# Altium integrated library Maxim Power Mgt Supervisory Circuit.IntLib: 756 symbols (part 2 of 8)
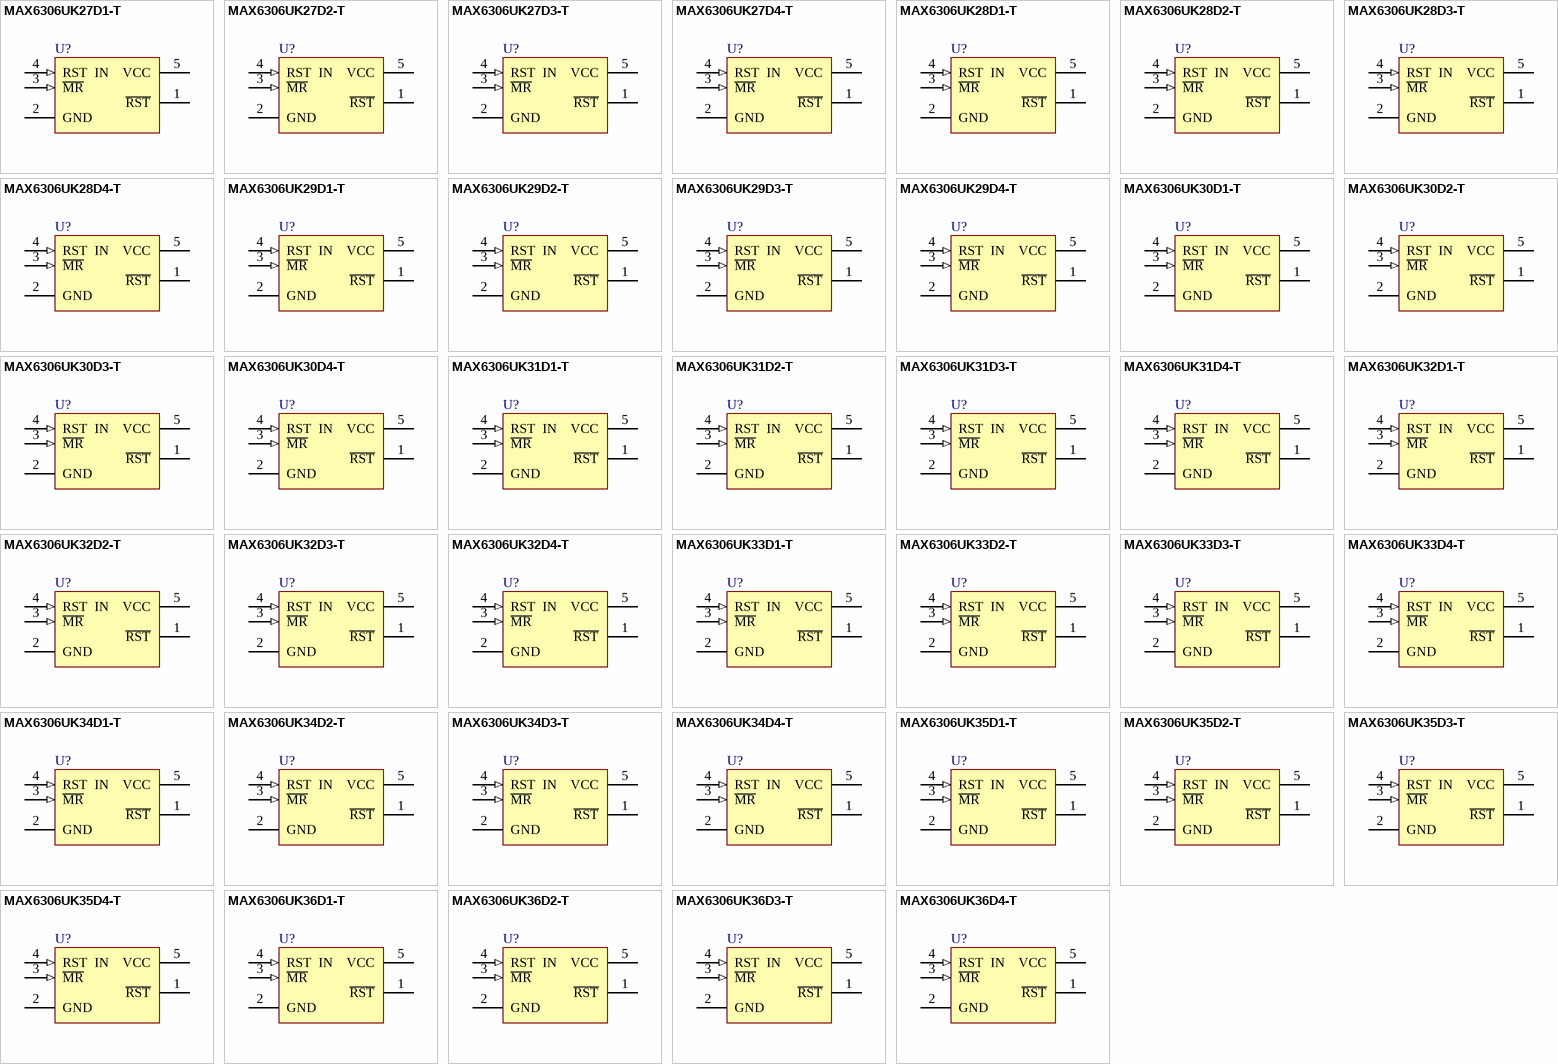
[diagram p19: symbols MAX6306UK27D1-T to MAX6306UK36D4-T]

## MAX6306UK34D4-T
designator U?
5-Pin, Multiple-Input, Programmable Reset IC
footprint SOT23-5_N (SOT23, 5-Leads, Body 2.9x1.6mm, Pitch 0.95mm, Lead Span 2.8mm, IPC Medium Density)
footprint SOT23-5_L (SOT23, 5-Leads, Body 2.9x1.6mm, Pitch 0.95mm, Lead Span 2.8mm, IPC High Density)
footprint SOT23-5_M (SOT23, 5-Leads, Body 2.9x1.6mm, Pitch 0.95mm, Lead Span 2.8mm, IPC Low Density)
pins: 1 ~{RST} (oc), 2 GND (power), 3 ~{MR} (in), 4 RST  IN (in), 5 VCC (power)

## MAX6306UK35D1-T
designator U?
5-Pin, Multiple-Input, Programmable Reset IC
footprint SOT23-5_N (SOT23, 5-Leads, Body 2.9x1.6mm, Pitch 0.95mm, Lead Span 2.8mm, IPC Medium Density)
footprint SOT23-5_L (SOT23, 5-Leads, Body 2.9x1.6mm, Pitch 0.95mm, Lead Span 2.8mm, IPC High Density)
footprint SOT23-5_M (SOT23, 5-Leads, Body 2.9x1.6mm, Pitch 0.95mm, Lead Span 2.8mm, IPC Low Density)
pins: 1 ~{RST} (oc), 2 GND (power), 3 ~{MR} (in), 4 RST  IN (in), 5 VCC (power)

## MAX6306UK35D2-T
designator U?
5-Pin, Multiple-Input, Programmable Reset IC
footprint SOT23-5_N (SOT23, 5-Leads, Body 2.9x1.6mm, Pitch 0.95mm, Lead Span 2.8mm, IPC Medium Density)
footprint SOT23-5_L (SOT23, 5-Leads, Body 2.9x1.6mm, Pitch 0.95mm, Lead Span 2.8mm, IPC High Density)
footprint SOT23-5_M (SOT23, 5-Leads, Body 2.9x1.6mm, Pitch 0.95mm, Lead Span 2.8mm, IPC Low Density)
pins: 1 ~{RST} (oc), 2 GND (power), 3 ~{MR} (in), 4 RST  IN (in), 5 VCC (power)

## MAX6306UK35D3-T
designator U?
5-Pin, Multiple-Input, Programmable Reset IC
footprint SOT23-5_N (SOT23, 5-Leads, Body 2.9x1.6mm, Pitch 0.95mm, Lead Span 2.8mm, IPC Medium Density)
footprint SOT23-5_L (SOT23, 5-Leads, Body 2.9x1.6mm, Pitch 0.95mm, Lead Span 2.8mm, IPC High Density)
footprint SOT23-5_M (SOT23, 5-Leads, Body 2.9x1.6mm, Pitch 0.95mm, Lead Span 2.8mm, IPC Low Density)
pins: 1 ~{RST} (oc), 2 GND (power), 3 ~{MR} (in), 4 RST  IN (in), 5 VCC (power)

## MAX6306UK35D4-T
designator U?
5-Pin, Multiple-Input, Programmable Reset IC
footprint SOT23-5_N (SOT23, 5-Leads, Body 2.9x1.6mm, Pitch 0.95mm, Lead Span 2.8mm, IPC Medium Density)
footprint SOT23-5_L (SOT23, 5-Leads, Body 2.9x1.6mm, Pitch 0.95mm, Lead Span 2.8mm, IPC High Density)
footprint SOT23-5_M (SOT23, 5-Leads, Body 2.9x1.6mm, Pitch 0.95mm, Lead Span 2.8mm, IPC Low Density)
pins: 1 ~{RST} (oc), 2 GND (power), 3 ~{MR} (in), 4 RST  IN (in), 5 VCC (power)

## MAX6306UK36D1-T
designator U?
5-Pin, Multiple-Input, Programmable Reset IC
footprint SOT23-5_N (SOT23, 5-Leads, Body 2.9x1.6mm, Pitch 0.95mm, Lead Span 2.8mm, IPC Medium Density)
footprint SOT23-5_L (SOT23, 5-Leads, Body 2.9x1.6mm, Pitch 0.95mm, Lead Span 2.8mm, IPC High Density)
footprint SOT23-5_M (SOT23, 5-Leads, Body 2.9x1.6mm, Pitch 0.95mm, Lead Span 2.8mm, IPC Low Density)
pins: 1 ~{RST} (oc), 2 GND (power), 3 ~{MR} (in), 4 RST  IN (in), 5 VCC (power)

## MAX6306UK36D2-T
designator U?
5-Pin, Multiple-Input, Programmable Reset IC
footprint SOT23-5_N (SOT23, 5-Leads, Body 2.9x1.6mm, Pitch 0.95mm, Lead Span 2.8mm, IPC Medium Density)
footprint SOT23-5_L (SOT23, 5-Leads, Body 2.9x1.6mm, Pitch 0.95mm, Lead Span 2.8mm, IPC High Density)
footprint SOT23-5_M (SOT23, 5-Leads, Body 2.9x1.6mm, Pitch 0.95mm, Lead Span 2.8mm, IPC Low Density)
pins: 1 ~{RST} (oc), 2 GND (power), 3 ~{MR} (in), 4 RST  IN (in), 5 VCC (power)

## MAX6306UK36D3-T
designator U?
5-Pin, Multiple-Input, Programmable Reset IC
footprint SOT23-5_N (SOT23, 5-Leads, Body 2.9x1.6mm, Pitch 0.95mm, Lead Span 2.8mm, IPC Medium Density)
footprint SOT23-5_L (SOT23, 5-Leads, Body 2.9x1.6mm, Pitch 0.95mm, Lead Span 2.8mm, IPC High Density)
footprint SOT23-5_M (SOT23, 5-Leads, Body 2.9x1.6mm, Pitch 0.95mm, Lead Span 2.8mm, IPC Low Density)
pins: 1 ~{RST} (oc), 2 GND (power), 3 ~{MR} (in), 4 RST  IN (in), 5 VCC (power)

## MAX6306UK36D4-T
designator U?
5-Pin, Multiple-Input, Programmable Reset IC
footprint SOT23-5_N (SOT23, 5-Leads, Body 2.9x1.6mm, Pitch 0.95mm, Lead Span 2.8mm, IPC Medium Density)
footprint SOT23-5_L (SOT23, 5-Leads, Body 2.9x1.6mm, Pitch 0.95mm, Lead Span 2.8mm, IPC High Density)
footprint SOT23-5_M (SOT23, 5-Leads, Body 2.9x1.6mm, Pitch 0.95mm, Lead Span 2.8mm, IPC Low Density)
pins: 1 ~{RST} (oc), 2 GND (power), 3 ~{MR} (in), 4 RST  IN (in), 5 VCC (power)

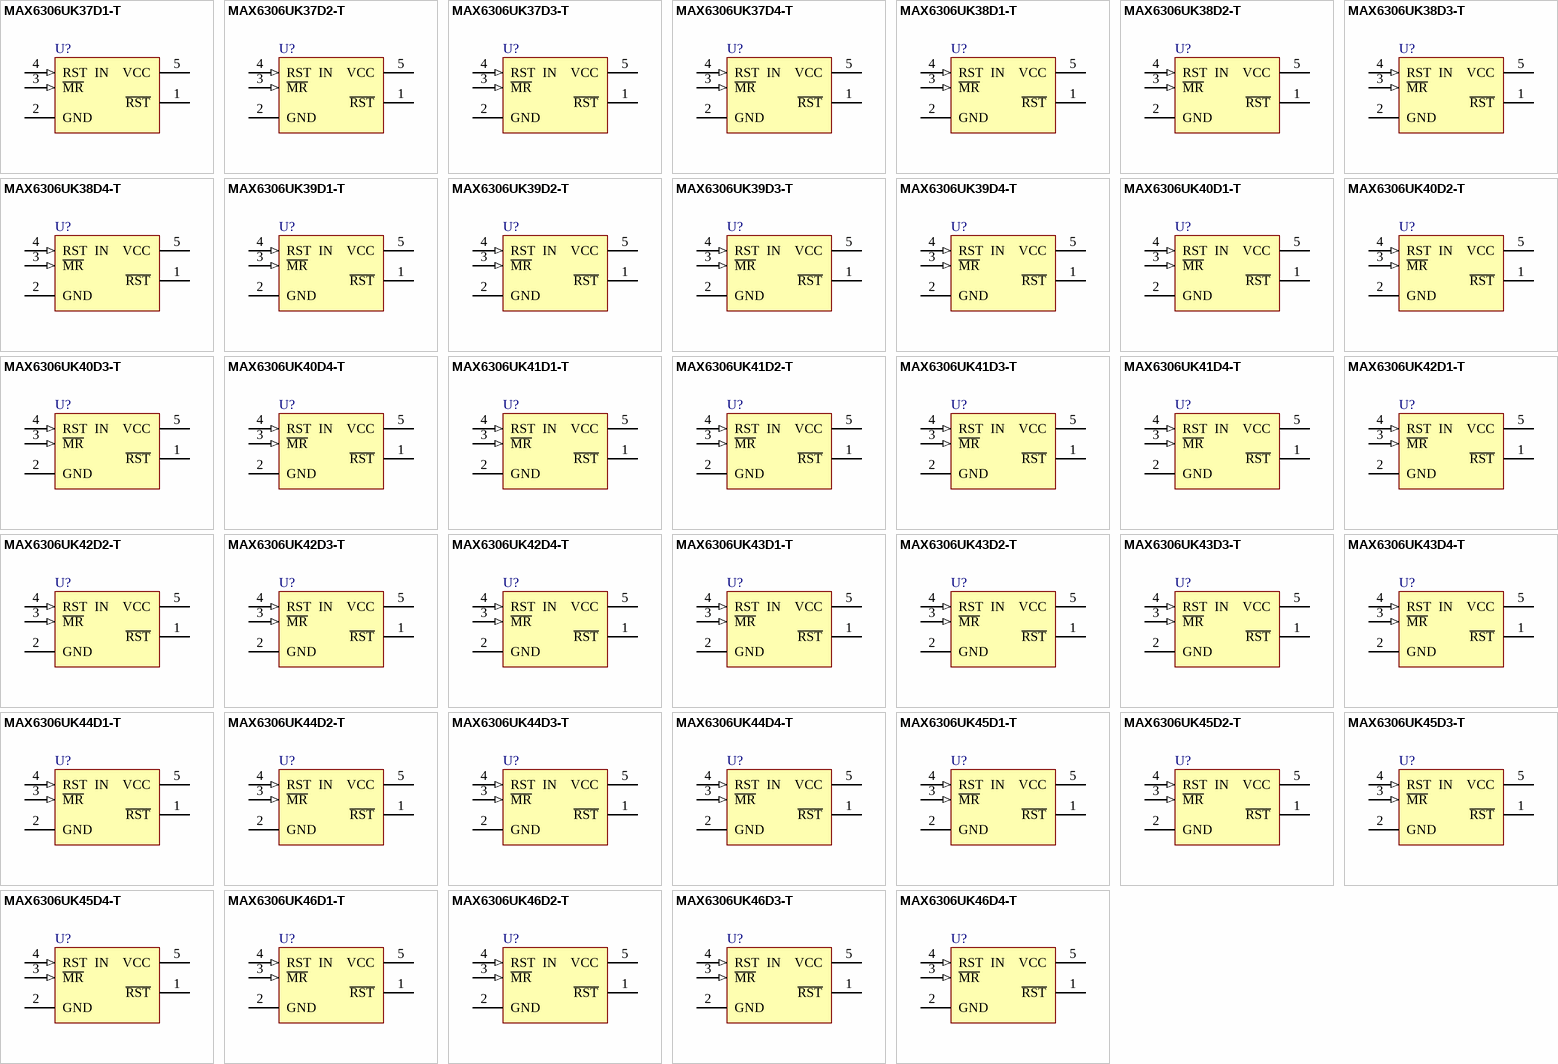
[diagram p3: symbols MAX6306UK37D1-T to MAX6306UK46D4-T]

## MAX6306UK37D1-T
designator U?
5-Pin, Multiple-Input, Programmable Reset IC
footprint SOT23-5_N (SOT23, 5-Leads, Body 2.9x1.6mm, Pitch 0.95mm, Lead Span 2.8mm, IPC Medium Density)
footprint SOT23-5_L (SOT23, 5-Leads, Body 2.9x1.6mm, Pitch 0.95mm, Lead Span 2.8mm, IPC High Density)
footprint SOT23-5_M (SOT23, 5-Leads, Body 2.9x1.6mm, Pitch 0.95mm, Lead Span 2.8mm, IPC Low Density)
pins: 1 ~{RST} (oc), 2 GND (power), 3 ~{MR} (in), 4 RST  IN (in), 5 VCC (power)

## MAX6306UK37D2-T
designator U?
5-Pin, Multiple-Input, Programmable Reset IC
footprint SOT23-5_N (SOT23, 5-Leads, Body 2.9x1.6mm, Pitch 0.95mm, Lead Span 2.8mm, IPC Medium Density)
footprint SOT23-5_L (SOT23, 5-Leads, Body 2.9x1.6mm, Pitch 0.95mm, Lead Span 2.8mm, IPC High Density)
footprint SOT23-5_M (SOT23, 5-Leads, Body 2.9x1.6mm, Pitch 0.95mm, Lead Span 2.8mm, IPC Low Density)
pins: 1 ~{RST} (oc), 2 GND (power), 3 ~{MR} (in), 4 RST  IN (in), 5 VCC (power)

## MAX6306UK37D3-T
designator U?
5-Pin, Multiple-Input, Programmable Reset IC
footprint SOT23-5_N (SOT23, 5-Leads, Body 2.9x1.6mm, Pitch 0.95mm, Lead Span 2.8mm, IPC Medium Density)
footprint SOT23-5_L (SOT23, 5-Leads, Body 2.9x1.6mm, Pitch 0.95mm, Lead Span 2.8mm, IPC High Density)
footprint SOT23-5_M (SOT23, 5-Leads, Body 2.9x1.6mm, Pitch 0.95mm, Lead Span 2.8mm, IPC Low Density)
pins: 1 ~{RST} (oc), 2 GND (power), 3 ~{MR} (in), 4 RST  IN (in), 5 VCC (power)

## MAX6306UK37D4-T
designator U?
5-Pin, Multiple-Input, Programmable Reset IC
footprint SOT23-5_N (SOT23, 5-Leads, Body 2.9x1.6mm, Pitch 0.95mm, Lead Span 2.8mm, IPC Medium Density)
footprint SOT23-5_L (SOT23, 5-Leads, Body 2.9x1.6mm, Pitch 0.95mm, Lead Span 2.8mm, IPC High Density)
footprint SOT23-5_M (SOT23, 5-Leads, Body 2.9x1.6mm, Pitch 0.95mm, Lead Span 2.8mm, IPC Low Density)
pins: 1 ~{RST} (oc), 2 GND (power), 3 ~{MR} (in), 4 RST  IN (in), 5 VCC (power)

## MAX6306UK38D1-T
designator U?
5-Pin, Multiple-Input, Programmable Reset IC
footprint SOT23-5_N (SOT23, 5-Leads, Body 2.9x1.6mm, Pitch 0.95mm, Lead Span 2.8mm, IPC Medium Density)
footprint SOT23-5_L (SOT23, 5-Leads, Body 2.9x1.6mm, Pitch 0.95mm, Lead Span 2.8mm, IPC High Density)
footprint SOT23-5_M (SOT23, 5-Leads, Body 2.9x1.6mm, Pitch 0.95mm, Lead Span 2.8mm, IPC Low Density)
pins: 1 ~{RST} (oc), 2 GND (power), 3 ~{MR} (in), 4 RST  IN (in), 5 VCC (power)

## MAX6306UK38D2-T
designator U?
5-Pin, Multiple-Input, Programmable Reset IC
footprint SOT23-5_N (SOT23, 5-Leads, Body 2.9x1.6mm, Pitch 0.95mm, Lead Span 2.8mm, IPC Medium Density)
footprint SOT23-5_L (SOT23, 5-Leads, Body 2.9x1.6mm, Pitch 0.95mm, Lead Span 2.8mm, IPC High Density)
footprint SOT23-5_M (SOT23, 5-Leads, Body 2.9x1.6mm, Pitch 0.95mm, Lead Span 2.8mm, IPC Low Density)
pins: 1 ~{RST} (oc), 2 GND (power), 3 ~{MR} (in), 4 RST  IN (in), 5 VCC (power)

## MAX6306UK38D3-T
designator U?
5-Pin, Multiple-Input, Programmable Reset IC
footprint SOT23-5_N (SOT23, 5-Leads, Body 2.9x1.6mm, Pitch 0.95mm, Lead Span 2.8mm, IPC Medium Density)
footprint SOT23-5_L (SOT23, 5-Leads, Body 2.9x1.6mm, Pitch 0.95mm, Lead Span 2.8mm, IPC High Density)
footprint SOT23-5_M (SOT23, 5-Leads, Body 2.9x1.6mm, Pitch 0.95mm, Lead Span 2.8mm, IPC Low Density)
pins: 1 ~{RST} (oc), 2 GND (power), 3 ~{MR} (in), 4 RST  IN (in), 5 VCC (power)

## MAX6306UK38D4-T
designator U?
5-Pin, Multiple-Input, Programmable Reset IC
footprint SOT23-5_N (SOT23, 5-Leads, Body 2.9x1.6mm, Pitch 0.95mm, Lead Span 2.8mm, IPC Medium Density)
footprint SOT23-5_L (SOT23, 5-Leads, Body 2.9x1.6mm, Pitch 0.95mm, Lead Span 2.8mm, IPC High Density)
footprint SOT23-5_M (SOT23, 5-Leads, Body 2.9x1.6mm, Pitch 0.95mm, Lead Span 2.8mm, IPC Low Density)
pins: 1 ~{RST} (oc), 2 GND (power), 3 ~{MR} (in), 4 RST  IN (in), 5 VCC (power)

## MAX6306UK39D1-T
designator U?
5-Pin, Multiple-Input, Programmable Reset IC
footprint SOT23-5_N (SOT23, 5-Leads, Body 2.9x1.6mm, Pitch 0.95mm, Lead Span 2.8mm, IPC Medium Density)
footprint SOT23-5_L (SOT23, 5-Leads, Body 2.9x1.6mm, Pitch 0.95mm, Lead Span 2.8mm, IPC High Density)
footprint SOT23-5_M (SOT23, 5-Leads, Body 2.9x1.6mm, Pitch 0.95mm, Lead Span 2.8mm, IPC Low Density)
pins: 1 ~{RST} (oc), 2 GND (power), 3 ~{MR} (in), 4 RST  IN (in), 5 VCC (power)

## MAX6306UK39D2-T
designator U?
5-Pin, Multiple-Input, Programmable Reset IC
footprint SOT23-5_N (SOT23, 5-Leads, Body 2.9x1.6mm, Pitch 0.95mm, Lead Span 2.8mm, IPC Medium Density)
footprint SOT23-5_L (SOT23, 5-Leads, Body 2.9x1.6mm, Pitch 0.95mm, Lead Span 2.8mm, IPC High Density)
footprint SOT23-5_M (SOT23, 5-Leads, Body 2.9x1.6mm, Pitch 0.95mm, Lead Span 2.8mm, IPC Low Density)
pins: 1 ~{RST} (oc), 2 GND (power), 3 ~{MR} (in), 4 RST  IN (in), 5 VCC (power)

## MAX6306UK39D3-T
designator U?
5-Pin, Multiple-Input, Programmable Reset IC
footprint SOT23-5_N (SOT23, 5-Leads, Body 2.9x1.6mm, Pitch 0.95mm, Lead Span 2.8mm, IPC Medium Density)
footprint SOT23-5_L (SOT23, 5-Leads, Body 2.9x1.6mm, Pitch 0.95mm, Lead Span 2.8mm, IPC High Density)
footprint SOT23-5_M (SOT23, 5-Leads, Body 2.9x1.6mm, Pitch 0.95mm, Lead Span 2.8mm, IPC Low Density)
pins: 1 ~{RST} (oc), 2 GND (power), 3 ~{MR} (in), 4 RST  IN (in), 5 VCC (power)

## MAX6306UK39D4-T
designator U?
5-Pin, Multiple-Input, Programmable Reset IC
footprint SOT23-5_N (SOT23, 5-Leads, Body 2.9x1.6mm, Pitch 0.95mm, Lead Span 2.8mm, IPC Medium Density)
footprint SOT23-5_L (SOT23, 5-Leads, Body 2.9x1.6mm, Pitch 0.95mm, Lead Span 2.8mm, IPC High Density)
footprint SOT23-5_M (SOT23, 5-Leads, Body 2.9x1.6mm, Pitch 0.95mm, Lead Span 2.8mm, IPC Low Density)
pins: 1 ~{RST} (oc), 2 GND (power), 3 ~{MR} (in), 4 RST  IN (in), 5 VCC (power)

## MAX6306UK40D1-T
designator U?
5-Pin, Multiple-Input, Programmable Reset IC
footprint SOT23-5_N (SOT23, 5-Leads, Body 2.9x1.6mm, Pitch 0.95mm, Lead Span 2.8mm, IPC Medium Density)
footprint SOT23-5_L (SOT23, 5-Leads, Body 2.9x1.6mm, Pitch 0.95mm, Lead Span 2.8mm, IPC High Density)
footprint SOT23-5_M (SOT23, 5-Leads, Body 2.9x1.6mm, Pitch 0.95mm, Lead Span 2.8mm, IPC Low Density)
pins: 1 ~{RST} (oc), 2 GND (power), 3 ~{MR} (in), 4 RST  IN (in), 5 VCC (power)

## MAX6306UK40D2-T
designator U?
5-Pin, Multiple-Input, Programmable Reset IC
footprint SOT23-5_N (SOT23, 5-Leads, Body 2.9x1.6mm, Pitch 0.95mm, Lead Span 2.8mm, IPC Medium Density)
footprint SOT23-5_L (SOT23, 5-Leads, Body 2.9x1.6mm, Pitch 0.95mm, Lead Span 2.8mm, IPC High Density)
footprint SOT23-5_M (SOT23, 5-Leads, Body 2.9x1.6mm, Pitch 0.95mm, Lead Span 2.8mm, IPC Low Density)
pins: 1 ~{RST} (oc), 2 GND (power), 3 ~{MR} (in), 4 RST  IN (in), 5 VCC (power)

## MAX6306UK40D3-T
designator U?
5-Pin, Multiple-Input, Programmable Reset IC
footprint SOT23-5_N (SOT23, 5-Leads, Body 2.9x1.6mm, Pitch 0.95mm, Lead Span 2.8mm, IPC Medium Density)
footprint SOT23-5_L (SOT23, 5-Leads, Body 2.9x1.6mm, Pitch 0.95mm, Lead Span 2.8mm, IPC High Density)
footprint SOT23-5_M (SOT23, 5-Leads, Body 2.9x1.6mm, Pitch 0.95mm, Lead Span 2.8mm, IPC Low Density)
pins: 1 ~{RST} (oc), 2 GND (power), 3 ~{MR} (in), 4 RST  IN (in), 5 VCC (power)

## MAX6306UK40D4-T
designator U?
5-Pin, Multiple-Input, Programmable Reset IC
footprint SOT23-5_N (SOT23, 5-Leads, Body 2.9x1.6mm, Pitch 0.95mm, Lead Span 2.8mm, IPC Medium Density)
footprint SOT23-5_L (SOT23, 5-Leads, Body 2.9x1.6mm, Pitch 0.95mm, Lead Span 2.8mm, IPC High Density)
footprint SOT23-5_M (SOT23, 5-Leads, Body 2.9x1.6mm, Pitch 0.95mm, Lead Span 2.8mm, IPC Low Density)
pins: 1 ~{RST} (oc), 2 GND (power), 3 ~{MR} (in), 4 RST  IN (in), 5 VCC (power)

## MAX6306UK41D1-T
designator U?
5-Pin, Multiple-Input, Programmable Reset IC
footprint SOT23-5_N (SOT23, 5-Leads, Body 2.9x1.6mm, Pitch 0.95mm, Lead Span 2.8mm, IPC Medium Density)
footprint SOT23-5_L (SOT23, 5-Leads, Body 2.9x1.6mm, Pitch 0.95mm, Lead Span 2.8mm, IPC High Density)
footprint SOT23-5_M (SOT23, 5-Leads, Body 2.9x1.6mm, Pitch 0.95mm, Lead Span 2.8mm, IPC Low Density)
pins: 1 ~{RST} (oc), 2 GND (power), 3 ~{MR} (in), 4 RST  IN (in), 5 VCC (power)

## MAX6306UK41D2-T
designator U?
5-Pin, Multiple-Input, Programmable Reset IC
footprint SOT23-5_N (SOT23, 5-Leads, Body 2.9x1.6mm, Pitch 0.95mm, Lead Span 2.8mm, IPC Medium Density)
footprint SOT23-5_L (SOT23, 5-Leads, Body 2.9x1.6mm, Pitch 0.95mm, Lead Span 2.8mm, IPC High Density)
footprint SOT23-5_M (SOT23, 5-Leads, Body 2.9x1.6mm, Pitch 0.95mm, Lead Span 2.8mm, IPC Low Density)
pins: 1 ~{RST} (oc), 2 GND (power), 3 ~{MR} (in), 4 RST  IN (in), 5 VCC (power)

## MAX6306UK41D3-T
designator U?
5-Pin, Multiple-Input, Programmable Reset IC
footprint SOT23-5_N (SOT23, 5-Leads, Body 2.9x1.6mm, Pitch 0.95mm, Lead Span 2.8mm, IPC Medium Density)
footprint SOT23-5_L (SOT23, 5-Leads, Body 2.9x1.6mm, Pitch 0.95mm, Lead Span 2.8mm, IPC High Density)
footprint SOT23-5_M (SOT23, 5-Leads, Body 2.9x1.6mm, Pitch 0.95mm, Lead Span 2.8mm, IPC Low Density)
pins: 1 ~{RST} (oc), 2 GND (power), 3 ~{MR} (in), 4 RST  IN (in), 5 VCC (power)

## MAX6306UK41D4-T
designator U?
5-Pin, Multiple-Input, Programmable Reset IC
footprint SOT23-5_N (SOT23, 5-Leads, Body 2.9x1.6mm, Pitch 0.95mm, Lead Span 2.8mm, IPC Medium Density)
footprint SOT23-5_L (SOT23, 5-Leads, Body 2.9x1.6mm, Pitch 0.95mm, Lead Span 2.8mm, IPC High Density)
footprint SOT23-5_M (SOT23, 5-Leads, Body 2.9x1.6mm, Pitch 0.95mm, Lead Span 2.8mm, IPC Low Density)
pins: 1 ~{RST} (oc), 2 GND (power), 3 ~{MR} (in), 4 RST  IN (in), 5 VCC (power)

## MAX6306UK42D1-T
designator U?
5-Pin, Multiple-Input, Programmable Reset IC
footprint SOT23-5_N (SOT23, 5-Leads, Body 2.9x1.6mm, Pitch 0.95mm, Lead Span 2.8mm, IPC Medium Density)
footprint SOT23-5_L (SOT23, 5-Leads, Body 2.9x1.6mm, Pitch 0.95mm, Lead Span 2.8mm, IPC High Density)
footprint SOT23-5_M (SOT23, 5-Leads, Body 2.9x1.6mm, Pitch 0.95mm, Lead Span 2.8mm, IPC Low Density)
pins: 1 ~{RST} (oc), 2 GND (power), 3 ~{MR} (in), 4 RST  IN (in), 5 VCC (power)

## MAX6306UK42D2-T
designator U?
5-Pin, Multiple-Input, Programmable Reset IC
footprint SOT23-5_N (SOT23, 5-Leads, Body 2.9x1.6mm, Pitch 0.95mm, Lead Span 2.8mm, IPC Medium Density)
footprint SOT23-5_L (SOT23, 5-Leads, Body 2.9x1.6mm, Pitch 0.95mm, Lead Span 2.8mm, IPC High Density)
footprint SOT23-5_M (SOT23, 5-Leads, Body 2.9x1.6mm, Pitch 0.95mm, Lead Span 2.8mm, IPC Low Density)
pins: 1 ~{RST} (oc), 2 GND (power), 3 ~{MR} (in), 4 RST  IN (in), 5 VCC (power)

## MAX6306UK42D3-T
designator U?
5-Pin, Multiple-Input, Programmable Reset IC
footprint SOT23-5_N (SOT23, 5-Leads, Body 2.9x1.6mm, Pitch 0.95mm, Lead Span 2.8mm, IPC Medium Density)
footprint SOT23-5_L (SOT23, 5-Leads, Body 2.9x1.6mm, Pitch 0.95mm, Lead Span 2.8mm, IPC High Density)
footprint SOT23-5_M (SOT23, 5-Leads, Body 2.9x1.6mm, Pitch 0.95mm, Lead Span 2.8mm, IPC Low Density)
pins: 1 ~{RST} (oc), 2 GND (power), 3 ~{MR} (in), 4 RST  IN (in), 5 VCC (power)

## MAX6306UK42D4-T
designator U?
5-Pin, Multiple-Input, Programmable Reset IC
footprint SOT23-5_N (SOT23, 5-Leads, Body 2.9x1.6mm, Pitch 0.95mm, Lead Span 2.8mm, IPC Medium Density)
footprint SOT23-5_L (SOT23, 5-Leads, Body 2.9x1.6mm, Pitch 0.95mm, Lead Span 2.8mm, IPC High Density)
footprint SOT23-5_M (SOT23, 5-Leads, Body 2.9x1.6mm, Pitch 0.95mm, Lead Span 2.8mm, IPC Low Density)
pins: 1 ~{RST} (oc), 2 GND (power), 3 ~{MR} (in), 4 RST  IN (in), 5 VCC (power)

## MAX6306UK43D1-T
designator U?
5-Pin, Multiple-Input, Programmable Reset IC
footprint SOT23-5_N (SOT23, 5-Leads, Body 2.9x1.6mm, Pitch 0.95mm, Lead Span 2.8mm, IPC Medium Density)
footprint SOT23-5_L (SOT23, 5-Leads, Body 2.9x1.6mm, Pitch 0.95mm, Lead Span 2.8mm, IPC High Density)
footprint SOT23-5_M (SOT23, 5-Leads, Body 2.9x1.6mm, Pitch 0.95mm, Lead Span 2.8mm, IPC Low Density)
pins: 1 ~{RST} (oc), 2 GND (power), 3 ~{MR} (in), 4 RST  IN (in), 5 VCC (power)

## MAX6306UK43D2-T
designator U?
5-Pin, Multiple-Input, Programmable Reset IC
footprint SOT23-5_N (SOT23, 5-Leads, Body 2.9x1.6mm, Pitch 0.95mm, Lead Span 2.8mm, IPC Medium Density)
footprint SOT23-5_L (SOT23, 5-Leads, Body 2.9x1.6mm, Pitch 0.95mm, Lead Span 2.8mm, IPC High Density)
footprint SOT23-5_M (SOT23, 5-Leads, Body 2.9x1.6mm, Pitch 0.95mm, Lead Span 2.8mm, IPC Low Density)
pins: 1 ~{RST} (oc), 2 GND (power), 3 ~{MR} (in), 4 RST  IN (in), 5 VCC (power)

## MAX6306UK43D3-T
designator U?
5-Pin, Multiple-Input, Programmable Reset IC
footprint SOT23-5_N (SOT23, 5-Leads, Body 2.9x1.6mm, Pitch 0.95mm, Lead Span 2.8mm, IPC Medium Density)
footprint SOT23-5_L (SOT23, 5-Leads, Body 2.9x1.6mm, Pitch 0.95mm, Lead Span 2.8mm, IPC High Density)
footprint SOT23-5_M (SOT23, 5-Leads, Body 2.9x1.6mm, Pitch 0.95mm, Lead Span 2.8mm, IPC Low Density)
pins: 1 ~{RST} (oc), 2 GND (power), 3 ~{MR} (in), 4 RST  IN (in), 5 VCC (power)

## MAX6306UK43D4-T
designator U?
5-Pin, Multiple-Input, Programmable Reset IC
footprint SOT23-5_N (SOT23, 5-Leads, Body 2.9x1.6mm, Pitch 0.95mm, Lead Span 2.8mm, IPC Medium Density)
footprint SOT23-5_L (SOT23, 5-Leads, Body 2.9x1.6mm, Pitch 0.95mm, Lead Span 2.8mm, IPC High Density)
footprint SOT23-5_M (SOT23, 5-Leads, Body 2.9x1.6mm, Pitch 0.95mm, Lead Span 2.8mm, IPC Low Density)
pins: 1 ~{RST} (oc), 2 GND (power), 3 ~{MR} (in), 4 RST  IN (in), 5 VCC (power)

## MAX6306UK44D1-T
designator U?
5-Pin, Multiple-Input, Programmable Reset IC
footprint SOT23-5_N (SOT23, 5-Leads, Body 2.9x1.6mm, Pitch 0.95mm, Lead Span 2.8mm, IPC Medium Density)
footprint SOT23-5_L (SOT23, 5-Leads, Body 2.9x1.6mm, Pitch 0.95mm, Lead Span 2.8mm, IPC High Density)
footprint SOT23-5_M (SOT23, 5-Leads, Body 2.9x1.6mm, Pitch 0.95mm, Lead Span 2.8mm, IPC Low Density)
pins: 1 ~{RST} (oc), 2 GND (power), 3 ~{MR} (in), 4 RST  IN (in), 5 VCC (power)

## MAX6306UK44D2-T
designator U?
5-Pin, Multiple-Input, Programmable Reset IC
footprint SOT23-5_N (SOT23, 5-Leads, Body 2.9x1.6mm, Pitch 0.95mm, Lead Span 2.8mm, IPC Medium Density)
footprint SOT23-5_L (SOT23, 5-Leads, Body 2.9x1.6mm, Pitch 0.95mm, Lead Span 2.8mm, IPC High Density)
footprint SOT23-5_M (SOT23, 5-Leads, Body 2.9x1.6mm, Pitch 0.95mm, Lead Span 2.8mm, IPC Low Density)
pins: 1 ~{RST} (oc), 2 GND (power), 3 ~{MR} (in), 4 RST  IN (in), 5 VCC (power)

## MAX6306UK44D3-T
designator U?
5-Pin, Multiple-Input, Programmable Reset IC
footprint SOT23-5_N (SOT23, 5-Leads, Body 2.9x1.6mm, Pitch 0.95mm, Lead Span 2.8mm, IPC Medium Density)
footprint SOT23-5_L (SOT23, 5-Leads, Body 2.9x1.6mm, Pitch 0.95mm, Lead Span 2.8mm, IPC High Density)
footprint SOT23-5_M (SOT23, 5-Leads, Body 2.9x1.6mm, Pitch 0.95mm, Lead Span 2.8mm, IPC Low Density)
pins: 1 ~{RST} (oc), 2 GND (power), 3 ~{MR} (in), 4 RST  IN (in), 5 VCC (power)

## MAX6306UK44D4-T
designator U?
5-Pin, Multiple-Input, Programmable Reset IC
footprint SOT23-5_N (SOT23, 5-Leads, Body 2.9x1.6mm, Pitch 0.95mm, Lead Span 2.8mm, IPC Medium Density)
footprint SOT23-5_L (SOT23, 5-Leads, Body 2.9x1.6mm, Pitch 0.95mm, Lead Span 2.8mm, IPC High Density)
footprint SOT23-5_M (SOT23, 5-Leads, Body 2.9x1.6mm, Pitch 0.95mm, Lead Span 2.8mm, IPC Low Density)
pins: 1 ~{RST} (oc), 2 GND (power), 3 ~{MR} (in), 4 RST  IN (in), 5 VCC (power)

## MAX6306UK45D1-T
designator U?
5-Pin, Multiple-Input, Programmable Reset IC
footprint SOT23-5_N (SOT23, 5-Leads, Body 2.9x1.6mm, Pitch 0.95mm, Lead Span 2.8mm, IPC Medium Density)
footprint SOT23-5_L (SOT23, 5-Leads, Body 2.9x1.6mm, Pitch 0.95mm, Lead Span 2.8mm, IPC High Density)
footprint SOT23-5_M (SOT23, 5-Leads, Body 2.9x1.6mm, Pitch 0.95mm, Lead Span 2.8mm, IPC Low Density)
pins: 1 ~{RST} (oc), 2 GND (power), 3 ~{MR} (in), 4 RST  IN (in), 5 VCC (power)

## MAX6306UK45D2-T
designator U?
5-Pin, Multiple-Input, Programmable Reset IC
footprint SOT23-5_N (SOT23, 5-Leads, Body 2.9x1.6mm, Pitch 0.95mm, Lead Span 2.8mm, IPC Medium Density)
footprint SOT23-5_L (SOT23, 5-Leads, Body 2.9x1.6mm, Pitch 0.95mm, Lead Span 2.8mm, IPC High Density)
footprint SOT23-5_M (SOT23, 5-Leads, Body 2.9x1.6mm, Pitch 0.95mm, Lead Span 2.8mm, IPC Low Density)
pins: 1 ~{RST} (oc), 2 GND (power), 3 ~{MR} (in), 4 RST  IN (in), 5 VCC (power)

## MAX6306UK45D3-T
designator U?
5-Pin, Multiple-Input, Programmable Reset IC
footprint SOT23-5_N (SOT23, 5-Leads, Body 2.9x1.6mm, Pitch 0.95mm, Lead Span 2.8mm, IPC Medium Density)
footprint SOT23-5_L (SOT23, 5-Leads, Body 2.9x1.6mm, Pitch 0.95mm, Lead Span 2.8mm, IPC High Density)
footprint SOT23-5_M (SOT23, 5-Leads, Body 2.9x1.6mm, Pitch 0.95mm, Lead Span 2.8mm, IPC Low Density)
pins: 1 ~{RST} (oc), 2 GND (power), 3 ~{MR} (in), 4 RST  IN (in), 5 VCC (power)

## MAX6306UK45D4-T
designator U?
5-Pin, Multiple-Input, Programmable Reset IC
footprint SOT23-5_N (SOT23, 5-Leads, Body 2.9x1.6mm, Pitch 0.95mm, Lead Span 2.8mm, IPC Medium Density)
footprint SOT23-5_L (SOT23, 5-Leads, Body 2.9x1.6mm, Pitch 0.95mm, Lead Span 2.8mm, IPC High Density)
footprint SOT23-5_M (SOT23, 5-Leads, Body 2.9x1.6mm, Pitch 0.95mm, Lead Span 2.8mm, IPC Low Density)
pins: 1 ~{RST} (oc), 2 GND (power), 3 ~{MR} (in), 4 RST  IN (in), 5 VCC (power)

## MAX6306UK46D1-T
designator U?
5-Pin, Multiple-Input, Programmable Reset IC
footprint SOT23-5_N (SOT23, 5-Leads, Body 2.9x1.6mm, Pitch 0.95mm, Lead Span 2.8mm, IPC Medium Density)
footprint SOT23-5_L (SOT23, 5-Leads, Body 2.9x1.6mm, Pitch 0.95mm, Lead Span 2.8mm, IPC High Density)
footprint SOT23-5_M (SOT23, 5-Leads, Body 2.9x1.6mm, Pitch 0.95mm, Lead Span 2.8mm, IPC Low Density)
pins: 1 ~{RST} (oc), 2 GND (power), 3 ~{MR} (in), 4 RST  IN (in), 5 VCC (power)

## MAX6306UK46D2-T
designator U?
5-Pin, Multiple-Input, Programmable Reset IC
footprint SOT23-5_N (SOT23, 5-Leads, Body 2.9x1.6mm, Pitch 0.95mm, Lead Span 2.8mm, IPC Medium Density)
footprint SOT23-5_L (SOT23, 5-Leads, Body 2.9x1.6mm, Pitch 0.95mm, Lead Span 2.8mm, IPC High Density)
footprint SOT23-5_M (SOT23, 5-Leads, Body 2.9x1.6mm, Pitch 0.95mm, Lead Span 2.8mm, IPC Low Density)
pins: 1 ~{RST} (oc), 2 GND (power), 3 ~{MR} (in), 4 RST  IN (in), 5 VCC (power)

## MAX6306UK46D3-T
designator U?
5-Pin, Multiple-Input, Programmable Reset IC
footprint SOT23-5_N (SOT23, 5-Leads, Body 2.9x1.6mm, Pitch 0.95mm, Lead Span 2.8mm, IPC Medium Density)
footprint SOT23-5_L (SOT23, 5-Leads, Body 2.9x1.6mm, Pitch 0.95mm, Lead Span 2.8mm, IPC High Density)
footprint SOT23-5_M (SOT23, 5-Leads, Body 2.9x1.6mm, Pitch 0.95mm, Lead Span 2.8mm, IPC Low Density)
pins: 1 ~{RST} (oc), 2 GND (power), 3 ~{MR} (in), 4 RST  IN (in), 5 VCC (power)

## MAX6306UK46D4-T
designator U?
5-Pin, Multiple-Input, Programmable Reset IC
footprint SOT23-5_N (SOT23, 5-Leads, Body 2.9x1.6mm, Pitch 0.95mm, Lead Span 2.8mm, IPC Medium Density)
footprint SOT23-5_L (SOT23, 5-Leads, Body 2.9x1.6mm, Pitch 0.95mm, Lead Span 2.8mm, IPC High Density)
footprint SOT23-5_M (SOT23, 5-Leads, Body 2.9x1.6mm, Pitch 0.95mm, Lead Span 2.8mm, IPC Low Density)
pins: 1 ~{RST} (oc), 2 GND (power), 3 ~{MR} (in), 4 RST  IN (in), 5 VCC (power)

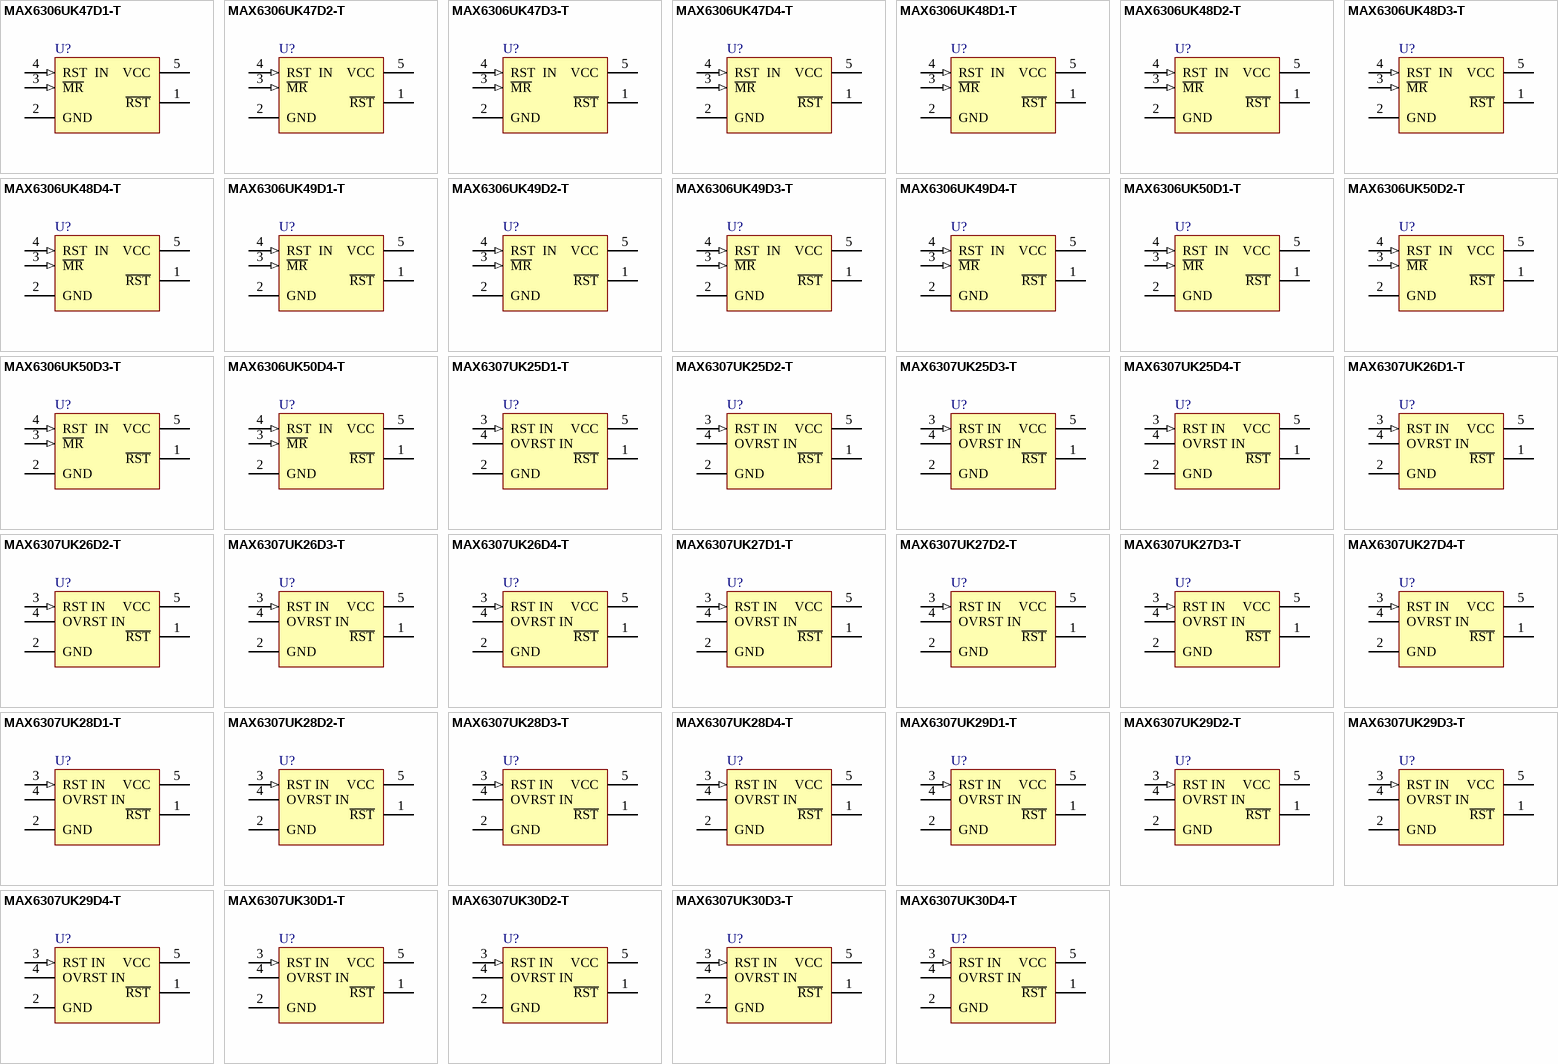
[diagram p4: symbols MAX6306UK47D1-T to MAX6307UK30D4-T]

## MAX6306UK47D1-T
designator U?
5-Pin, Multiple-Input, Programmable Reset IC
footprint SOT23-5_N (SOT23, 5-Leads, Body 2.9x1.6mm, Pitch 0.95mm, Lead Span 2.8mm, IPC Medium Density)
footprint SOT23-5_L (SOT23, 5-Leads, Body 2.9x1.6mm, Pitch 0.95mm, Lead Span 2.8mm, IPC High Density)
footprint SOT23-5_M (SOT23, 5-Leads, Body 2.9x1.6mm, Pitch 0.95mm, Lead Span 2.8mm, IPC Low Density)
pins: 1 ~{RST} (oc), 2 GND (power), 3 ~{MR} (in), 4 RST  IN (in), 5 VCC (power)

## MAX6306UK47D2-T
designator U?
5-Pin, Multiple-Input, Programmable Reset IC
footprint SOT23-5_N (SOT23, 5-Leads, Body 2.9x1.6mm, Pitch 0.95mm, Lead Span 2.8mm, IPC Medium Density)
footprint SOT23-5_L (SOT23, 5-Leads, Body 2.9x1.6mm, Pitch 0.95mm, Lead Span 2.8mm, IPC High Density)
footprint SOT23-5_M (SOT23, 5-Leads, Body 2.9x1.6mm, Pitch 0.95mm, Lead Span 2.8mm, IPC Low Density)
pins: 1 ~{RST} (oc), 2 GND (power), 3 ~{MR} (in), 4 RST  IN (in), 5 VCC (power)

## MAX6306UK47D3-T
designator U?
5-Pin, Multiple-Input, Programmable Reset IC
footprint SOT23-5_N (SOT23, 5-Leads, Body 2.9x1.6mm, Pitch 0.95mm, Lead Span 2.8mm, IPC Medium Density)
footprint SOT23-5_L (SOT23, 5-Leads, Body 2.9x1.6mm, Pitch 0.95mm, Lead Span 2.8mm, IPC High Density)
footprint SOT23-5_M (SOT23, 5-Leads, Body 2.9x1.6mm, Pitch 0.95mm, Lead Span 2.8mm, IPC Low Density)
pins: 1 ~{RST} (oc), 2 GND (power), 3 ~{MR} (in), 4 RST  IN (in), 5 VCC (power)

## MAX6306UK47D4-T
designator U?
5-Pin, Multiple-Input, Programmable Reset IC
footprint SOT23-5_N (SOT23, 5-Leads, Body 2.9x1.6mm, Pitch 0.95mm, Lead Span 2.8mm, IPC Medium Density)
footprint SOT23-5_L (SOT23, 5-Leads, Body 2.9x1.6mm, Pitch 0.95mm, Lead Span 2.8mm, IPC High Density)
footprint SOT23-5_M (SOT23, 5-Leads, Body 2.9x1.6mm, Pitch 0.95mm, Lead Span 2.8mm, IPC Low Density)
pins: 1 ~{RST} (oc), 2 GND (power), 3 ~{MR} (in), 4 RST  IN (in), 5 VCC (power)

## MAX6306UK48D1-T
designator U?
5-Pin, Multiple-Input, Programmable Reset IC
footprint SOT23-5_N (SOT23, 5-Leads, Body 2.9x1.6mm, Pitch 0.95mm, Lead Span 2.8mm, IPC Medium Density)
footprint SOT23-5_L (SOT23, 5-Leads, Body 2.9x1.6mm, Pitch 0.95mm, Lead Span 2.8mm, IPC High Density)
footprint SOT23-5_M (SOT23, 5-Leads, Body 2.9x1.6mm, Pitch 0.95mm, Lead Span 2.8mm, IPC Low Density)
pins: 1 ~{RST} (oc), 2 GND (power), 3 ~{MR} (in), 4 RST  IN (in), 5 VCC (power)

## MAX6306UK48D2-T
designator U?
5-Pin, Multiple-Input, Programmable Reset IC
footprint SOT23-5_N (SOT23, 5-Leads, Body 2.9x1.6mm, Pitch 0.95mm, Lead Span 2.8mm, IPC Medium Density)
footprint SOT23-5_L (SOT23, 5-Leads, Body 2.9x1.6mm, Pitch 0.95mm, Lead Span 2.8mm, IPC High Density)
footprint SOT23-5_M (SOT23, 5-Leads, Body 2.9x1.6mm, Pitch 0.95mm, Lead Span 2.8mm, IPC Low Density)
pins: 1 ~{RST} (oc), 2 GND (power), 3 ~{MR} (in), 4 RST  IN (in), 5 VCC (power)

## MAX6306UK48D3-T
designator U?
5-Pin, Multiple-Input, Programmable Reset IC
footprint SOT23-5_N (SOT23, 5-Leads, Body 2.9x1.6mm, Pitch 0.95mm, Lead Span 2.8mm, IPC Medium Density)
footprint SOT23-5_L (SOT23, 5-Leads, Body 2.9x1.6mm, Pitch 0.95mm, Lead Span 2.8mm, IPC High Density)
footprint SOT23-5_M (SOT23, 5-Leads, Body 2.9x1.6mm, Pitch 0.95mm, Lead Span 2.8mm, IPC Low Density)
pins: 1 ~{RST} (oc), 2 GND (power), 3 ~{MR} (in), 4 RST  IN (in), 5 VCC (power)

## MAX6306UK48D4-T
designator U?
5-Pin, Multiple-Input, Programmable Reset IC
footprint SOT23-5_N (SOT23, 5-Leads, Body 2.9x1.6mm, Pitch 0.95mm, Lead Span 2.8mm, IPC Medium Density)
footprint SOT23-5_L (SOT23, 5-Leads, Body 2.9x1.6mm, Pitch 0.95mm, Lead Span 2.8mm, IPC High Density)
footprint SOT23-5_M (SOT23, 5-Leads, Body 2.9x1.6mm, Pitch 0.95mm, Lead Span 2.8mm, IPC Low Density)
pins: 1 ~{RST} (oc), 2 GND (power), 3 ~{MR} (in), 4 RST  IN (in), 5 VCC (power)

## MAX6306UK49D1-T
designator U?
5-Pin, Multiple-Input, Programmable Reset IC
footprint SOT23-5_N (SOT23, 5-Leads, Body 2.9x1.6mm, Pitch 0.95mm, Lead Span 2.8mm, IPC Medium Density)
footprint SOT23-5_L (SOT23, 5-Leads, Body 2.9x1.6mm, Pitch 0.95mm, Lead Span 2.8mm, IPC High Density)
footprint SOT23-5_M (SOT23, 5-Leads, Body 2.9x1.6mm, Pitch 0.95mm, Lead Span 2.8mm, IPC Low Density)
pins: 1 ~{RST} (oc), 2 GND (power), 3 ~{MR} (in), 4 RST  IN (in), 5 VCC (power)

## MAX6306UK49D2-T
designator U?
5-Pin, Multiple-Input, Programmable Reset IC
footprint SOT23-5_N (SOT23, 5-Leads, Body 2.9x1.6mm, Pitch 0.95mm, Lead Span 2.8mm, IPC Medium Density)
footprint SOT23-5_L (SOT23, 5-Leads, Body 2.9x1.6mm, Pitch 0.95mm, Lead Span 2.8mm, IPC High Density)
footprint SOT23-5_M (SOT23, 5-Leads, Body 2.9x1.6mm, Pitch 0.95mm, Lead Span 2.8mm, IPC Low Density)
pins: 1 ~{RST} (oc), 2 GND (power), 3 ~{MR} (in), 4 RST  IN (in), 5 VCC (power)

## MAX6306UK49D3-T
designator U?
5-Pin, Multiple-Input, Programmable Reset IC
footprint SOT23-5_N (SOT23, 5-Leads, Body 2.9x1.6mm, Pitch 0.95mm, Lead Span 2.8mm, IPC Medium Density)
footprint SOT23-5_L (SOT23, 5-Leads, Body 2.9x1.6mm, Pitch 0.95mm, Lead Span 2.8mm, IPC High Density)
footprint SOT23-5_M (SOT23, 5-Leads, Body 2.9x1.6mm, Pitch 0.95mm, Lead Span 2.8mm, IPC Low Density)
pins: 1 ~{RST} (oc), 2 GND (power), 3 ~{MR} (in), 4 RST  IN (in), 5 VCC (power)

## MAX6306UK49D4-T
designator U?
5-Pin, Multiple-Input, Programmable Reset IC
footprint SOT23-5_N (SOT23, 5-Leads, Body 2.9x1.6mm, Pitch 0.95mm, Lead Span 2.8mm, IPC Medium Density)
footprint SOT23-5_L (SOT23, 5-Leads, Body 2.9x1.6mm, Pitch 0.95mm, Lead Span 2.8mm, IPC High Density)
footprint SOT23-5_M (SOT23, 5-Leads, Body 2.9x1.6mm, Pitch 0.95mm, Lead Span 2.8mm, IPC Low Density)
pins: 1 ~{RST} (oc), 2 GND (power), 3 ~{MR} (in), 4 RST  IN (in), 5 VCC (power)

## MAX6306UK50D1-T
designator U?
5-Pin, Multiple-Input, Programmable Reset IC
footprint SOT23-5_N (SOT23, 5-Leads, Body 2.9x1.6mm, Pitch 0.95mm, Lead Span 2.8mm, IPC Medium Density)
footprint SOT23-5_L (SOT23, 5-Leads, Body 2.9x1.6mm, Pitch 0.95mm, Lead Span 2.8mm, IPC High Density)
footprint SOT23-5_M (SOT23, 5-Leads, Body 2.9x1.6mm, Pitch 0.95mm, Lead Span 2.8mm, IPC Low Density)
pins: 1 ~{RST} (oc), 2 GND (power), 3 ~{MR} (in), 4 RST  IN (in), 5 VCC (power)

## MAX6306UK50D2-T
designator U?
5-Pin, Multiple-Input, Programmable Reset IC
footprint SOT23-5_N (SOT23, 5-Leads, Body 2.9x1.6mm, Pitch 0.95mm, Lead Span 2.8mm, IPC Medium Density)
footprint SOT23-5_L (SOT23, 5-Leads, Body 2.9x1.6mm, Pitch 0.95mm, Lead Span 2.8mm, IPC High Density)
footprint SOT23-5_M (SOT23, 5-Leads, Body 2.9x1.6mm, Pitch 0.95mm, Lead Span 2.8mm, IPC Low Density)
pins: 1 ~{RST} (oc), 2 GND (power), 3 ~{MR} (in), 4 RST  IN (in), 5 VCC (power)

## MAX6306UK50D3-T
designator U?
5-Pin, Multiple-Input, Programmable Reset IC
footprint SOT23-5_N (SOT23, 5-Leads, Body 2.9x1.6mm, Pitch 0.95mm, Lead Span 2.8mm, IPC Medium Density)
footprint SOT23-5_L (SOT23, 5-Leads, Body 2.9x1.6mm, Pitch 0.95mm, Lead Span 2.8mm, IPC High Density)
footprint SOT23-5_M (SOT23, 5-Leads, Body 2.9x1.6mm, Pitch 0.95mm, Lead Span 2.8mm, IPC Low Density)
pins: 1 ~{RST} (oc), 2 GND (power), 3 ~{MR} (in), 4 RST  IN (in), 5 VCC (power)

## MAX6306UK50D4-T
designator U?
5-Pin, Multiple-Input, Programmable Reset IC
footprint SOT23-5_N (SOT23, 5-Leads, Body 2.9x1.6mm, Pitch 0.95mm, Lead Span 2.8mm, IPC Medium Density)
footprint SOT23-5_L (SOT23, 5-Leads, Body 2.9x1.6mm, Pitch 0.95mm, Lead Span 2.8mm, IPC High Density)
footprint SOT23-5_M (SOT23, 5-Leads, Body 2.9x1.6mm, Pitch 0.95mm, Lead Span 2.8mm, IPC Low Density)
pins: 1 ~{RST} (oc), 2 GND (power), 3 ~{MR} (in), 4 RST  IN (in), 5 VCC (power)

## MAX6307UK25D1-T
designator U?
5-Pin, Multiple-Input, Programmable Reset IC
footprint SOT23-5_N (SOT23, 5-Leads, Body 2.9x1.6mm, Pitch 0.95mm, Lead Span 2.8mm, IPC Medium Density)
footprint SOT23-5_L (SOT23, 5-Leads, Body 2.9x1.6mm, Pitch 0.95mm, Lead Span 2.8mm, IPC High Density)
footprint SOT23-5_M (SOT23, 5-Leads, Body 2.9x1.6mm, Pitch 0.95mm, Lead Span 2.8mm, IPC Low Density)
pins: 1 ~{RST} (oc), 2 GND (power), 3 RST IN (in), 4 OVRST IN, 5 VCC (power)

## MAX6307UK25D2-T
designator U?
5-Pin, Multiple-Input, Programmable Reset IC
footprint SOT23-5_N (SOT23, 5-Leads, Body 2.9x1.6mm, Pitch 0.95mm, Lead Span 2.8mm, IPC Medium Density)
footprint SOT23-5_L (SOT23, 5-Leads, Body 2.9x1.6mm, Pitch 0.95mm, Lead Span 2.8mm, IPC High Density)
footprint SOT23-5_M (SOT23, 5-Leads, Body 2.9x1.6mm, Pitch 0.95mm, Lead Span 2.8mm, IPC Low Density)
pins: 1 ~{RST} (oc), 2 GND (power), 3 RST IN (in), 4 OVRST IN, 5 VCC (power)

## MAX6307UK25D3-T
designator U?
5-Pin, Multiple-Input, Programmable Reset IC
footprint SOT23-5_N (SOT23, 5-Leads, Body 2.9x1.6mm, Pitch 0.95mm, Lead Span 2.8mm, IPC Medium Density)
footprint SOT23-5_L (SOT23, 5-Leads, Body 2.9x1.6mm, Pitch 0.95mm, Lead Span 2.8mm, IPC High Density)
footprint SOT23-5_M (SOT23, 5-Leads, Body 2.9x1.6mm, Pitch 0.95mm, Lead Span 2.8mm, IPC Low Density)
pins: 1 ~{RST} (oc), 2 GND (power), 3 RST IN (in), 4 OVRST IN, 5 VCC (power)

## MAX6307UK25D4-T
designator U?
5-Pin, Multiple-Input, Programmable Reset IC
footprint SOT23-5_N (SOT23, 5-Leads, Body 2.9x1.6mm, Pitch 0.95mm, Lead Span 2.8mm, IPC Medium Density)
footprint SOT23-5_L (SOT23, 5-Leads, Body 2.9x1.6mm, Pitch 0.95mm, Lead Span 2.8mm, IPC High Density)
footprint SOT23-5_M (SOT23, 5-Leads, Body 2.9x1.6mm, Pitch 0.95mm, Lead Span 2.8mm, IPC Low Density)
pins: 1 ~{RST} (oc), 2 GND (power), 3 RST IN (in), 4 OVRST IN, 5 VCC (power)

## MAX6307UK26D1-T
designator U?
5-Pin, Multiple-Input, Programmable Reset IC
footprint SOT23-5_N (SOT23, 5-Leads, Body 2.9x1.6mm, Pitch 0.95mm, Lead Span 2.8mm, IPC Medium Density)
footprint SOT23-5_L (SOT23, 5-Leads, Body 2.9x1.6mm, Pitch 0.95mm, Lead Span 2.8mm, IPC High Density)
footprint SOT23-5_M (SOT23, 5-Leads, Body 2.9x1.6mm, Pitch 0.95mm, Lead Span 2.8mm, IPC Low Density)
pins: 1 ~{RST} (oc), 2 GND (power), 3 RST IN (in), 4 OVRST IN, 5 VCC (power)

## MAX6307UK26D2-T
designator U?
5-Pin, Multiple-Input, Programmable Reset IC
footprint SOT23-5_N (SOT23, 5-Leads, Body 2.9x1.6mm, Pitch 0.95mm, Lead Span 2.8mm, IPC Medium Density)
footprint SOT23-5_L (SOT23, 5-Leads, Body 2.9x1.6mm, Pitch 0.95mm, Lead Span 2.8mm, IPC High Density)
footprint SOT23-5_M (SOT23, 5-Leads, Body 2.9x1.6mm, Pitch 0.95mm, Lead Span 2.8mm, IPC Low Density)
pins: 1 ~{RST} (oc), 2 GND (power), 3 RST IN (in), 4 OVRST IN, 5 VCC (power)

## MAX6307UK26D3-T
designator U?
5-Pin, Multiple-Input, Programmable Reset IC
footprint SOT23-5_N (SOT23, 5-Leads, Body 2.9x1.6mm, Pitch 0.95mm, Lead Span 2.8mm, IPC Medium Density)
footprint SOT23-5_L (SOT23, 5-Leads, Body 2.9x1.6mm, Pitch 0.95mm, Lead Span 2.8mm, IPC High Density)
footprint SOT23-5_M (SOT23, 5-Leads, Body 2.9x1.6mm, Pitch 0.95mm, Lead Span 2.8mm, IPC Low Density)
pins: 1 ~{RST} (oc), 2 GND (power), 3 RST IN (in), 4 OVRST IN, 5 VCC (power)

## MAX6307UK26D4-T
designator U?
5-Pin, Multiple-Input, Programmable Reset IC
footprint SOT23-5_N (SOT23, 5-Leads, Body 2.9x1.6mm, Pitch 0.95mm, Lead Span 2.8mm, IPC Medium Density)
footprint SOT23-5_L (SOT23, 5-Leads, Body 2.9x1.6mm, Pitch 0.95mm, Lead Span 2.8mm, IPC High Density)
footprint SOT23-5_M (SOT23, 5-Leads, Body 2.9x1.6mm, Pitch 0.95mm, Lead Span 2.8mm, IPC Low Density)
pins: 1 ~{RST} (oc), 2 GND (power), 3 RST IN (in), 4 OVRST IN, 5 VCC (power)

## MAX6307UK27D1-T
designator U?
5-Pin, Multiple-Input, Programmable Reset IC
footprint SOT23-5_N (SOT23, 5-Leads, Body 2.9x1.6mm, Pitch 0.95mm, Lead Span 2.8mm, IPC Medium Density)
footprint SOT23-5_L (SOT23, 5-Leads, Body 2.9x1.6mm, Pitch 0.95mm, Lead Span 2.8mm, IPC High Density)
footprint SOT23-5_M (SOT23, 5-Leads, Body 2.9x1.6mm, Pitch 0.95mm, Lead Span 2.8mm, IPC Low Density)
pins: 1 ~{RST} (oc), 2 GND (power), 3 RST IN (in), 4 OVRST IN, 5 VCC (power)

## MAX6307UK27D2-T
designator U?
5-Pin, Multiple-Input, Programmable Reset IC
footprint SOT23-5_N (SOT23, 5-Leads, Body 2.9x1.6mm, Pitch 0.95mm, Lead Span 2.8mm, IPC Medium Density)
footprint SOT23-5_L (SOT23, 5-Leads, Body 2.9x1.6mm, Pitch 0.95mm, Lead Span 2.8mm, IPC High Density)
footprint SOT23-5_M (SOT23, 5-Leads, Body 2.9x1.6mm, Pitch 0.95mm, Lead Span 2.8mm, IPC Low Density)
pins: 1 ~{RST} (oc), 2 GND (power), 3 RST IN (in), 4 OVRST IN, 5 VCC (power)

## MAX6307UK27D3-T
designator U?
5-Pin, Multiple-Input, Programmable Reset IC
footprint SOT23-5_N (SOT23, 5-Leads, Body 2.9x1.6mm, Pitch 0.95mm, Lead Span 2.8mm, IPC Medium Density)
footprint SOT23-5_L (SOT23, 5-Leads, Body 2.9x1.6mm, Pitch 0.95mm, Lead Span 2.8mm, IPC High Density)
footprint SOT23-5_M (SOT23, 5-Leads, Body 2.9x1.6mm, Pitch 0.95mm, Lead Span 2.8mm, IPC Low Density)
pins: 1 ~{RST} (oc), 2 GND (power), 3 RST IN (in), 4 OVRST IN, 5 VCC (power)

## MAX6307UK27D4-T
designator U?
5-Pin, Multiple-Input, Programmable Reset IC
footprint SOT23-5_N (SOT23, 5-Leads, Body 2.9x1.6mm, Pitch 0.95mm, Lead Span 2.8mm, IPC Medium Density)
footprint SOT23-5_L (SOT23, 5-Leads, Body 2.9x1.6mm, Pitch 0.95mm, Lead Span 2.8mm, IPC High Density)
footprint SOT23-5_M (SOT23, 5-Leads, Body 2.9x1.6mm, Pitch 0.95mm, Lead Span 2.8mm, IPC Low Density)
pins: 1 ~{RST} (oc), 2 GND (power), 3 RST IN (in), 4 OVRST IN, 5 VCC (power)

## MAX6307UK28D1-T
designator U?
5-Pin, Multiple-Input, Programmable Reset IC
footprint SOT23-5_N (SOT23, 5-Leads, Body 2.9x1.6mm, Pitch 0.95mm, Lead Span 2.8mm, IPC Medium Density)
footprint SOT23-5_L (SOT23, 5-Leads, Body 2.9x1.6mm, Pitch 0.95mm, Lead Span 2.8mm, IPC High Density)
footprint SOT23-5_M (SOT23, 5-Leads, Body 2.9x1.6mm, Pitch 0.95mm, Lead Span 2.8mm, IPC Low Density)
pins: 1 ~{RST} (oc), 2 GND (power), 3 RST IN (in), 4 OVRST IN, 5 VCC (power)

## MAX6307UK28D2-T
designator U?
5-Pin, Multiple-Input, Programmable Reset IC
footprint SOT23-5_N (SOT23, 5-Leads, Body 2.9x1.6mm, Pitch 0.95mm, Lead Span 2.8mm, IPC Medium Density)
footprint SOT23-5_L (SOT23, 5-Leads, Body 2.9x1.6mm, Pitch 0.95mm, Lead Span 2.8mm, IPC High Density)
footprint SOT23-5_M (SOT23, 5-Leads, Body 2.9x1.6mm, Pitch 0.95mm, Lead Span 2.8mm, IPC Low Density)
pins: 1 ~{RST} (oc), 2 GND (power), 3 RST IN (in), 4 OVRST IN, 5 VCC (power)

## MAX6307UK28D3-T
designator U?
5-Pin, Multiple-Input, Programmable Reset IC
footprint SOT23-5_N (SOT23, 5-Leads, Body 2.9x1.6mm, Pitch 0.95mm, Lead Span 2.8mm, IPC Medium Density)
footprint SOT23-5_L (SOT23, 5-Leads, Body 2.9x1.6mm, Pitch 0.95mm, Lead Span 2.8mm, IPC High Density)
footprint SOT23-5_M (SOT23, 5-Leads, Body 2.9x1.6mm, Pitch 0.95mm, Lead Span 2.8mm, IPC Low Density)
pins: 1 ~{RST} (oc), 2 GND (power), 3 RST IN (in), 4 OVRST IN, 5 VCC (power)

## MAX6307UK28D4-T
designator U?
5-Pin, Multiple-Input, Programmable Reset IC
footprint SOT23-5_N (SOT23, 5-Leads, Body 2.9x1.6mm, Pitch 0.95mm, Lead Span 2.8mm, IPC Medium Density)
footprint SOT23-5_L (SOT23, 5-Leads, Body 2.9x1.6mm, Pitch 0.95mm, Lead Span 2.8mm, IPC High Density)
footprint SOT23-5_M (SOT23, 5-Leads, Body 2.9x1.6mm, Pitch 0.95mm, Lead Span 2.8mm, IPC Low Density)
pins: 1 ~{RST} (oc), 2 GND (power), 3 RST IN (in), 4 OVRST IN, 5 VCC (power)

## MAX6307UK29D1-T
designator U?
5-Pin, Multiple-Input, Programmable Reset IC
footprint SOT23-5_N (SOT23, 5-Leads, Body 2.9x1.6mm, Pitch 0.95mm, Lead Span 2.8mm, IPC Medium Density)
footprint SOT23-5_L (SOT23, 5-Leads, Body 2.9x1.6mm, Pitch 0.95mm, Lead Span 2.8mm, IPC High Density)
footprint SOT23-5_M (SOT23, 5-Leads, Body 2.9x1.6mm, Pitch 0.95mm, Lead Span 2.8mm, IPC Low Density)
pins: 1 ~{RST} (oc), 2 GND (power), 3 RST IN (in), 4 OVRST IN, 5 VCC (power)

## MAX6307UK29D2-T
designator U?
5-Pin, Multiple-Input, Programmable Reset IC
footprint SOT23-5_N (SOT23, 5-Leads, Body 2.9x1.6mm, Pitch 0.95mm, Lead Span 2.8mm, IPC Medium Density)
footprint SOT23-5_L (SOT23, 5-Leads, Body 2.9x1.6mm, Pitch 0.95mm, Lead Span 2.8mm, IPC High Density)
footprint SOT23-5_M (SOT23, 5-Leads, Body 2.9x1.6mm, Pitch 0.95mm, Lead Span 2.8mm, IPC Low Density)
pins: 1 ~{RST} (oc), 2 GND (power), 3 RST IN (in), 4 OVRST IN, 5 VCC (power)

## MAX6307UK29D3-T
designator U?
5-Pin, Multiple-Input, Programmable Reset IC
footprint SOT23-5_N (SOT23, 5-Leads, Body 2.9x1.6mm, Pitch 0.95mm, Lead Span 2.8mm, IPC Medium Density)
footprint SOT23-5_L (SOT23, 5-Leads, Body 2.9x1.6mm, Pitch 0.95mm, Lead Span 2.8mm, IPC High Density)
footprint SOT23-5_M (SOT23, 5-Leads, Body 2.9x1.6mm, Pitch 0.95mm, Lead Span 2.8mm, IPC Low Density)
pins: 1 ~{RST} (oc), 2 GND (power), 3 RST IN (in), 4 OVRST IN, 5 VCC (power)

## MAX6307UK29D4-T
designator U?
5-Pin, Multiple-Input, Programmable Reset IC
footprint SOT23-5_N (SOT23, 5-Leads, Body 2.9x1.6mm, Pitch 0.95mm, Lead Span 2.8mm, IPC Medium Density)
footprint SOT23-5_L (SOT23, 5-Leads, Body 2.9x1.6mm, Pitch 0.95mm, Lead Span 2.8mm, IPC High Density)
footprint SOT23-5_M (SOT23, 5-Leads, Body 2.9x1.6mm, Pitch 0.95mm, Lead Span 2.8mm, IPC Low Density)
pins: 1 ~{RST} (oc), 2 GND (power), 3 RST IN (in), 4 OVRST IN, 5 VCC (power)

## MAX6307UK30D1-T
designator U?
5-Pin, Multiple-Input, Programmable Reset IC
footprint SOT23-5_N (SOT23, 5-Leads, Body 2.9x1.6mm, Pitch 0.95mm, Lead Span 2.8mm, IPC Medium Density)
footprint SOT23-5_L (SOT23, 5-Leads, Body 2.9x1.6mm, Pitch 0.95mm, Lead Span 2.8mm, IPC High Density)
footprint SOT23-5_M (SOT23, 5-Leads, Body 2.9x1.6mm, Pitch 0.95mm, Lead Span 2.8mm, IPC Low Density)
pins: 1 ~{RST} (oc), 2 GND (power), 3 RST IN (in), 4 OVRST IN, 5 VCC (power)

## MAX6307UK30D2-T
designator U?
5-Pin, Multiple-Input, Programmable Reset IC
footprint SOT23-5_N (SOT23, 5-Leads, Body 2.9x1.6mm, Pitch 0.95mm, Lead Span 2.8mm, IPC Medium Density)
footprint SOT23-5_L (SOT23, 5-Leads, Body 2.9x1.6mm, Pitch 0.95mm, Lead Span 2.8mm, IPC High Density)
footprint SOT23-5_M (SOT23, 5-Leads, Body 2.9x1.6mm, Pitch 0.95mm, Lead Span 2.8mm, IPC Low Density)
pins: 1 ~{RST} (oc), 2 GND (power), 3 RST IN (in), 4 OVRST IN, 5 VCC (power)

## MAX6307UK30D3-T
designator U?
5-Pin, Multiple-Input, Programmable Reset IC
footprint SOT23-5_N (SOT23, 5-Leads, Body 2.9x1.6mm, Pitch 0.95mm, Lead Span 2.8mm, IPC Medium Density)
footprint SOT23-5_L (SOT23, 5-Leads, Body 2.9x1.6mm, Pitch 0.95mm, Lead Span 2.8mm, IPC High Density)
footprint SOT23-5_M (SOT23, 5-Leads, Body 2.9x1.6mm, Pitch 0.95mm, Lead Span 2.8mm, IPC Low Density)
pins: 1 ~{RST} (oc), 2 GND (power), 3 RST IN (in), 4 OVRST IN, 5 VCC (power)

## MAX6307UK30D4-T
designator U?
5-Pin, Multiple-Input, Programmable Reset IC
footprint SOT23-5_N (SOT23, 5-Leads, Body 2.9x1.6mm, Pitch 0.95mm, Lead Span 2.8mm, IPC Medium Density)
footprint SOT23-5_L (SOT23, 5-Leads, Body 2.9x1.6mm, Pitch 0.95mm, Lead Span 2.8mm, IPC High Density)
footprint SOT23-5_M (SOT23, 5-Leads, Body 2.9x1.6mm, Pitch 0.95mm, Lead Span 2.8mm, IPC Low Density)
pins: 1 ~{RST} (oc), 2 GND (power), 3 RST IN (in), 4 OVRST IN, 5 VCC (power)

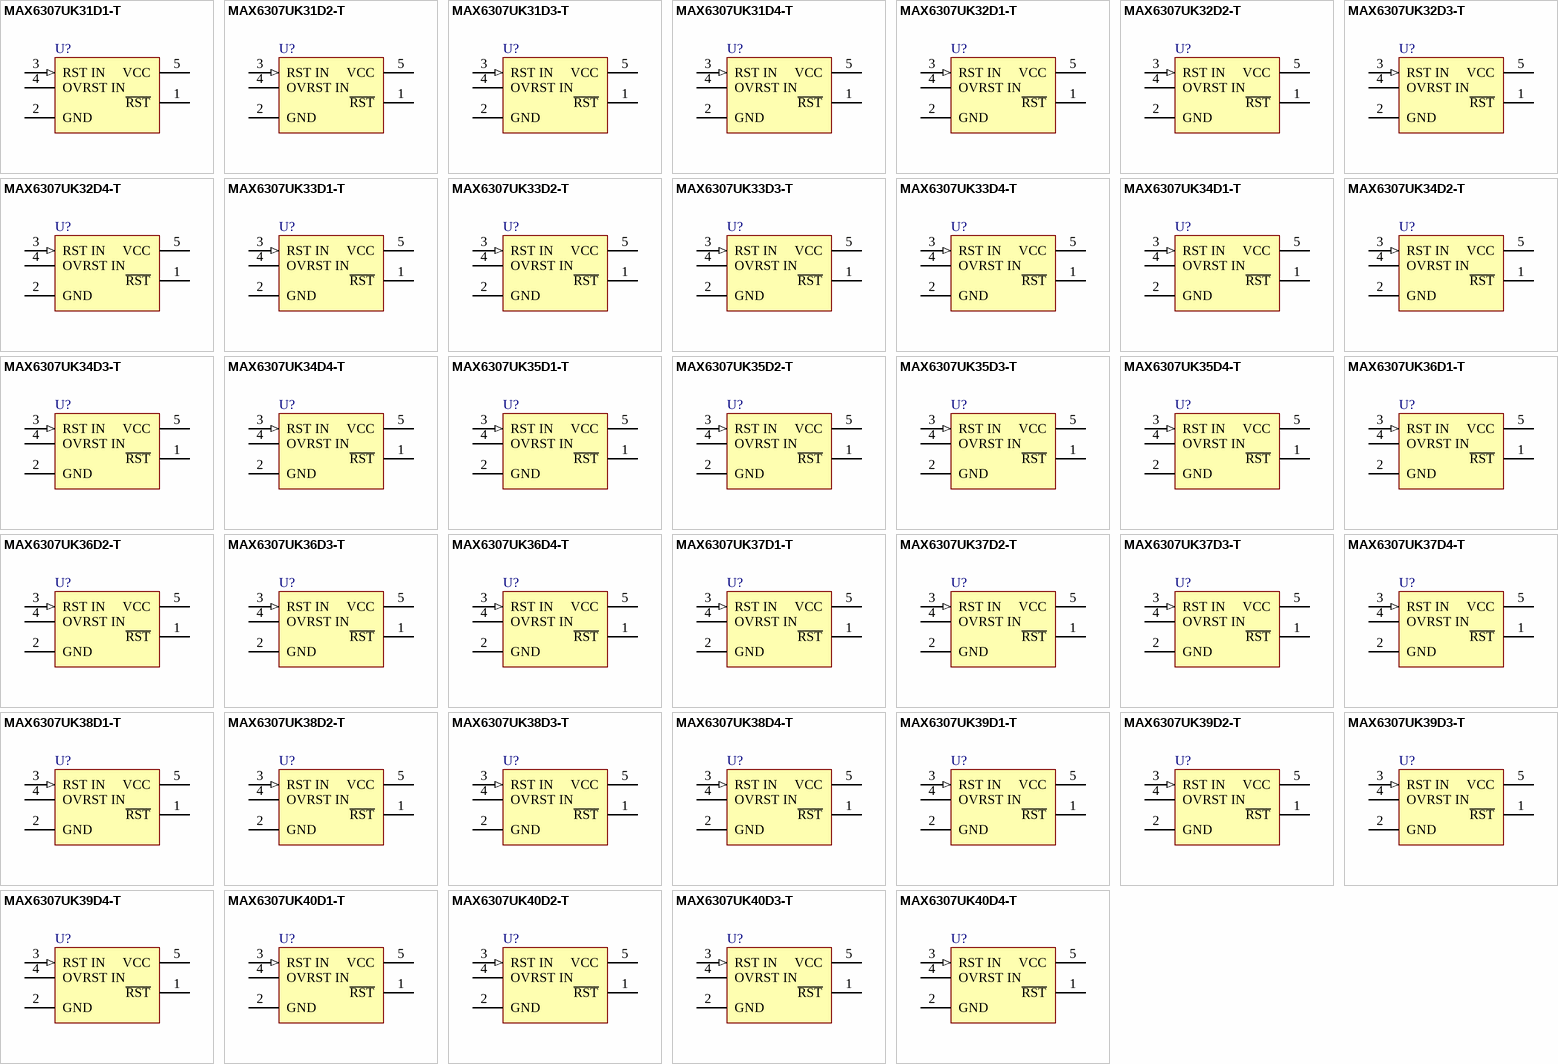
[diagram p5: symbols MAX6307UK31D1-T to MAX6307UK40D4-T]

## MAX6307UK31D1-T
designator U?
5-Pin, Multiple-Input, Programmable Reset IC
footprint SOT23-5_N (SOT23, 5-Leads, Body 2.9x1.6mm, Pitch 0.95mm, Lead Span 2.8mm, IPC Medium Density)
footprint SOT23-5_L (SOT23, 5-Leads, Body 2.9x1.6mm, Pitch 0.95mm, Lead Span 2.8mm, IPC High Density)
footprint SOT23-5_M (SOT23, 5-Leads, Body 2.9x1.6mm, Pitch 0.95mm, Lead Span 2.8mm, IPC Low Density)
pins: 1 ~{RST} (oc), 2 GND (power), 3 RST IN (in), 4 OVRST IN, 5 VCC (power)

## MAX6307UK31D2-T
designator U?
5-Pin, Multiple-Input, Programmable Reset IC
footprint SOT23-5_N (SOT23, 5-Leads, Body 2.9x1.6mm, Pitch 0.95mm, Lead Span 2.8mm, IPC Medium Density)
footprint SOT23-5_L (SOT23, 5-Leads, Body 2.9x1.6mm, Pitch 0.95mm, Lead Span 2.8mm, IPC High Density)
footprint SOT23-5_M (SOT23, 5-Leads, Body 2.9x1.6mm, Pitch 0.95mm, Lead Span 2.8mm, IPC Low Density)
pins: 1 ~{RST} (oc), 2 GND (power), 3 RST IN (in), 4 OVRST IN, 5 VCC (power)

## MAX6307UK31D3-T
designator U?
5-Pin, Multiple-Input, Programmable Reset IC
footprint SOT23-5_N (SOT23, 5-Leads, Body 2.9x1.6mm, Pitch 0.95mm, Lead Span 2.8mm, IPC Medium Density)
footprint SOT23-5_L (SOT23, 5-Leads, Body 2.9x1.6mm, Pitch 0.95mm, Lead Span 2.8mm, IPC High Density)
footprint SOT23-5_M (SOT23, 5-Leads, Body 2.9x1.6mm, Pitch 0.95mm, Lead Span 2.8mm, IPC Low Density)
pins: 1 ~{RST} (oc), 2 GND (power), 3 RST IN (in), 4 OVRST IN, 5 VCC (power)

## MAX6307UK31D4-T
designator U?
5-Pin, Multiple-Input, Programmable Reset IC
footprint SOT23-5_N (SOT23, 5-Leads, Body 2.9x1.6mm, Pitch 0.95mm, Lead Span 2.8mm, IPC Medium Density)
footprint SOT23-5_L (SOT23, 5-Leads, Body 2.9x1.6mm, Pitch 0.95mm, Lead Span 2.8mm, IPC High Density)
footprint SOT23-5_M (SOT23, 5-Leads, Body 2.9x1.6mm, Pitch 0.95mm, Lead Span 2.8mm, IPC Low Density)
pins: 1 ~{RST} (oc), 2 GND (power), 3 RST IN (in), 4 OVRST IN, 5 VCC (power)

## MAX6307UK32D1-T
designator U?
5-Pin, Multiple-Input, Programmable Reset IC
footprint SOT23-5_N (SOT23, 5-Leads, Body 2.9x1.6mm, Pitch 0.95mm, Lead Span 2.8mm, IPC Medium Density)
footprint SOT23-5_L (SOT23, 5-Leads, Body 2.9x1.6mm, Pitch 0.95mm, Lead Span 2.8mm, IPC High Density)
footprint SOT23-5_M (SOT23, 5-Leads, Body 2.9x1.6mm, Pitch 0.95mm, Lead Span 2.8mm, IPC Low Density)
pins: 1 ~{RST} (oc), 2 GND (power), 3 RST IN (in), 4 OVRST IN, 5 VCC (power)

## MAX6307UK32D2-T
designator U?
5-Pin, Multiple-Input, Programmable Reset IC
footprint SOT23-5_N (SOT23, 5-Leads, Body 2.9x1.6mm, Pitch 0.95mm, Lead Span 2.8mm, IPC Medium Density)
footprint SOT23-5_L (SOT23, 5-Leads, Body 2.9x1.6mm, Pitch 0.95mm, Lead Span 2.8mm, IPC High Density)
footprint SOT23-5_M (SOT23, 5-Leads, Body 2.9x1.6mm, Pitch 0.95mm, Lead Span 2.8mm, IPC Low Density)
pins: 1 ~{RST} (oc), 2 GND (power), 3 RST IN (in), 4 OVRST IN, 5 VCC (power)

## MAX6307UK32D3-T
designator U?
5-Pin, Multiple-Input, Programmable Reset IC
footprint SOT23-5_N (SOT23, 5-Leads, Body 2.9x1.6mm, Pitch 0.95mm, Lead Span 2.8mm, IPC Medium Density)
footprint SOT23-5_L (SOT23, 5-Leads, Body 2.9x1.6mm, Pitch 0.95mm, Lead Span 2.8mm, IPC High Density)
footprint SOT23-5_M (SOT23, 5-Leads, Body 2.9x1.6mm, Pitch 0.95mm, Lead Span 2.8mm, IPC Low Density)
pins: 1 ~{RST} (oc), 2 GND (power), 3 RST IN (in), 4 OVRST IN, 5 VCC (power)

## MAX6307UK32D4-T
designator U?
5-Pin, Multiple-Input, Programmable Reset IC
footprint SOT23-5_N (SOT23, 5-Leads, Body 2.9x1.6mm, Pitch 0.95mm, Lead Span 2.8mm, IPC Medium Density)
footprint SOT23-5_L (SOT23, 5-Leads, Body 2.9x1.6mm, Pitch 0.95mm, Lead Span 2.8mm, IPC High Density)
footprint SOT23-5_M (SOT23, 5-Leads, Body 2.9x1.6mm, Pitch 0.95mm, Lead Span 2.8mm, IPC Low Density)
pins: 1 ~{RST} (oc), 2 GND (power), 3 RST IN (in), 4 OVRST IN, 5 VCC (power)

## MAX6307UK33D1-T
designator U?
5-Pin, Multiple-Input, Programmable Reset IC
footprint SOT23-5_N (SOT23, 5-Leads, Body 2.9x1.6mm, Pitch 0.95mm, Lead Span 2.8mm, IPC Medium Density)
footprint SOT23-5_L (SOT23, 5-Leads, Body 2.9x1.6mm, Pitch 0.95mm, Lead Span 2.8mm, IPC High Density)
footprint SOT23-5_M (SOT23, 5-Leads, Body 2.9x1.6mm, Pitch 0.95mm, Lead Span 2.8mm, IPC Low Density)
pins: 1 ~{RST} (oc), 2 GND (power), 3 RST IN (in), 4 OVRST IN, 5 VCC (power)

## MAX6307UK33D2-T
designator U?
5-Pin, Multiple-Input, Programmable Reset IC
footprint SOT23-5_N (SOT23, 5-Leads, Body 2.9x1.6mm, Pitch 0.95mm, Lead Span 2.8mm, IPC Medium Density)
footprint SOT23-5_L (SOT23, 5-Leads, Body 2.9x1.6mm, Pitch 0.95mm, Lead Span 2.8mm, IPC High Density)
footprint SOT23-5_M (SOT23, 5-Leads, Body 2.9x1.6mm, Pitch 0.95mm, Lead Span 2.8mm, IPC Low Density)
pins: 1 ~{RST} (oc), 2 GND (power), 3 RST IN (in), 4 OVRST IN, 5 VCC (power)

## MAX6307UK33D3-T
designator U?
5-Pin, Multiple-Input, Programmable Reset IC
footprint SOT23-5_N (SOT23, 5-Leads, Body 2.9x1.6mm, Pitch 0.95mm, Lead Span 2.8mm, IPC Medium Density)
footprint SOT23-5_L (SOT23, 5-Leads, Body 2.9x1.6mm, Pitch 0.95mm, Lead Span 2.8mm, IPC High Density)
footprint SOT23-5_M (SOT23, 5-Leads, Body 2.9x1.6mm, Pitch 0.95mm, Lead Span 2.8mm, IPC Low Density)
pins: 1 ~{RST} (oc), 2 GND (power), 3 RST IN (in), 4 OVRST IN, 5 VCC (power)

## MAX6307UK33D4-T
designator U?
5-Pin, Multiple-Input, Programmable Reset IC
footprint SOT23-5_N (SOT23, 5-Leads, Body 2.9x1.6mm, Pitch 0.95mm, Lead Span 2.8mm, IPC Medium Density)
footprint SOT23-5_L (SOT23, 5-Leads, Body 2.9x1.6mm, Pitch 0.95mm, Lead Span 2.8mm, IPC High Density)
footprint SOT23-5_M (SOT23, 5-Leads, Body 2.9x1.6mm, Pitch 0.95mm, Lead Span 2.8mm, IPC Low Density)
pins: 1 ~{RST} (oc), 2 GND (power), 3 RST IN (in), 4 OVRST IN, 5 VCC (power)

## MAX6307UK34D1-T
designator U?
5-Pin, Multiple-Input, Programmable Reset IC
footprint SOT23-5_N (SOT23, 5-Leads, Body 2.9x1.6mm, Pitch 0.95mm, Lead Span 2.8mm, IPC Medium Density)
footprint SOT23-5_L (SOT23, 5-Leads, Body 2.9x1.6mm, Pitch 0.95mm, Lead Span 2.8mm, IPC High Density)
footprint SOT23-5_M (SOT23, 5-Leads, Body 2.9x1.6mm, Pitch 0.95mm, Lead Span 2.8mm, IPC Low Density)
pins: 1 ~{RST} (oc), 2 GND (power), 3 RST IN (in), 4 OVRST IN, 5 VCC (power)

## MAX6307UK34D2-T
designator U?
5-Pin, Multiple-Input, Programmable Reset IC
footprint SOT23-5_N (SOT23, 5-Leads, Body 2.9x1.6mm, Pitch 0.95mm, Lead Span 2.8mm, IPC Medium Density)
footprint SOT23-5_L (SOT23, 5-Leads, Body 2.9x1.6mm, Pitch 0.95mm, Lead Span 2.8mm, IPC High Density)
footprint SOT23-5_M (SOT23, 5-Leads, Body 2.9x1.6mm, Pitch 0.95mm, Lead Span 2.8mm, IPC Low Density)
pins: 1 ~{RST} (oc), 2 GND (power), 3 RST IN (in), 4 OVRST IN, 5 VCC (power)

## MAX6307UK34D3-T
designator U?
5-Pin, Multiple-Input, Programmable Reset IC
footprint SOT23-5_N (SOT23, 5-Leads, Body 2.9x1.6mm, Pitch 0.95mm, Lead Span 2.8mm, IPC Medium Density)
footprint SOT23-5_L (SOT23, 5-Leads, Body 2.9x1.6mm, Pitch 0.95mm, Lead Span 2.8mm, IPC High Density)
footprint SOT23-5_M (SOT23, 5-Leads, Body 2.9x1.6mm, Pitch 0.95mm, Lead Span 2.8mm, IPC Low Density)
pins: 1 ~{RST} (oc), 2 GND (power), 3 RST IN (in), 4 OVRST IN, 5 VCC (power)

## MAX6307UK34D4-T
designator U?
5-Pin, Multiple-Input, Programmable Reset IC
footprint SOT23-5_N (SOT23, 5-Leads, Body 2.9x1.6mm, Pitch 0.95mm, Lead Span 2.8mm, IPC Medium Density)
footprint SOT23-5_L (SOT23, 5-Leads, Body 2.9x1.6mm, Pitch 0.95mm, Lead Span 2.8mm, IPC High Density)
footprint SOT23-5_M (SOT23, 5-Leads, Body 2.9x1.6mm, Pitch 0.95mm, Lead Span 2.8mm, IPC Low Density)
pins: 1 ~{RST} (oc), 2 GND (power), 3 RST IN (in), 4 OVRST IN, 5 VCC (power)

## MAX6307UK35D1-T
designator U?
5-Pin, Multiple-Input, Programmable Reset IC
footprint SOT23-5_N (SOT23, 5-Leads, Body 2.9x1.6mm, Pitch 0.95mm, Lead Span 2.8mm, IPC Medium Density)
footprint SOT23-5_L (SOT23, 5-Leads, Body 2.9x1.6mm, Pitch 0.95mm, Lead Span 2.8mm, IPC High Density)
footprint SOT23-5_M (SOT23, 5-Leads, Body 2.9x1.6mm, Pitch 0.95mm, Lead Span 2.8mm, IPC Low Density)
pins: 1 ~{RST} (oc), 2 GND (power), 3 RST IN (in), 4 OVRST IN, 5 VCC (power)

## MAX6307UK35D2-T
designator U?
5-Pin, Multiple-Input, Programmable Reset IC
footprint SOT23-5_N (SOT23, 5-Leads, Body 2.9x1.6mm, Pitch 0.95mm, Lead Span 2.8mm, IPC Medium Density)
footprint SOT23-5_L (SOT23, 5-Leads, Body 2.9x1.6mm, Pitch 0.95mm, Lead Span 2.8mm, IPC High Density)
footprint SOT23-5_M (SOT23, 5-Leads, Body 2.9x1.6mm, Pitch 0.95mm, Lead Span 2.8mm, IPC Low Density)
pins: 1 ~{RST} (oc), 2 GND (power), 3 RST IN (in), 4 OVRST IN, 5 VCC (power)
